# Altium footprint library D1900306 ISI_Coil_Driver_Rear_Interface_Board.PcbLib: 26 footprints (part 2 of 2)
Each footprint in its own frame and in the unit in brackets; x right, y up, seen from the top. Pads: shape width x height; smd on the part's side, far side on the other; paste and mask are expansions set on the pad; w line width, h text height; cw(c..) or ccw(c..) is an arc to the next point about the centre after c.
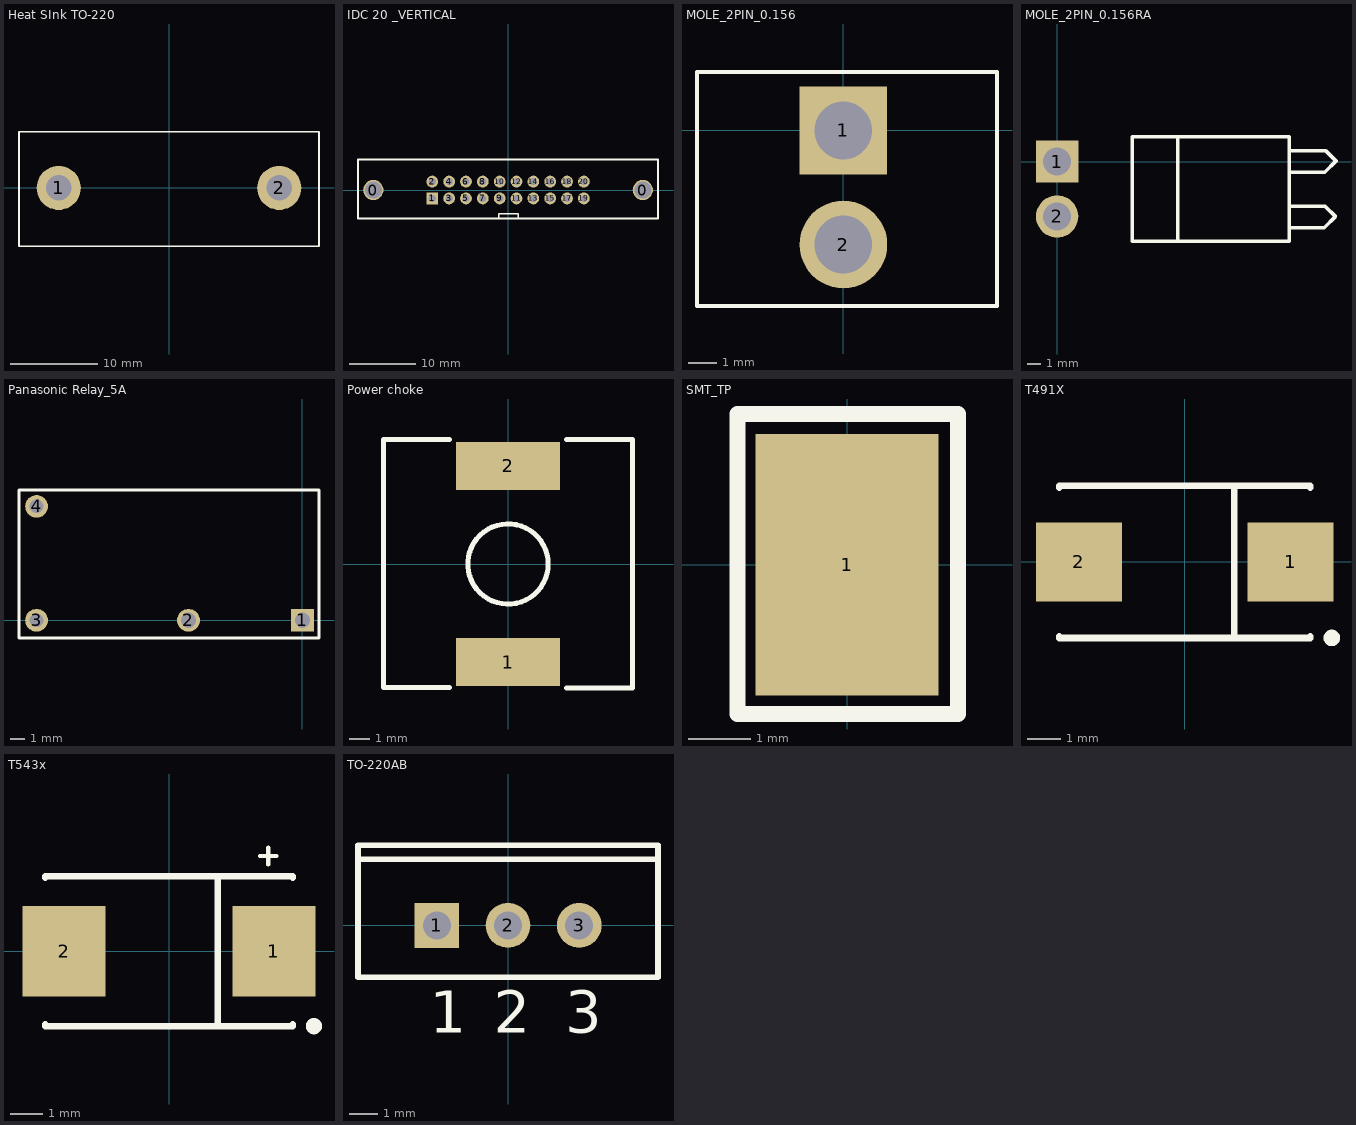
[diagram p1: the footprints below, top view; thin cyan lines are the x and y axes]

## Heat SInk TO-220 [mil]
pads (2):
  round 200 hole 115: 1(-500,0) 2(500,0)
Top Overlay:
  lines w8: -680,-265 680,-265 680,255 -680,255 -680,-265
3D body "T220-38E.step": height 1500, standoff -137.8, extent -669.61,-251.75 669.63,251.65

## IDC 20 _VERTICAL [mil]
pads (22):
  round 120 hole 100: 0(-800,0) 0(800,0)
  rect 70x70 hole 43: 1(-450,-50)
  round 70 hole 43: 2(-450,50) 3(-350,-50) 4(-350,50) 5(-250,-50) 6(-250,50) 7(-150,-50) 8(-150,50) 9(-50,-50) 10(-50,50) 11(50,-50) 12(50,50) 13(150,-50) 14(150,50) 15(250,-50) 16(250,50) 17(350,-50) 18(350,50) 19(450,-50) 20(450,50)
Top Overlay:
  lines w10: -55,-170 -55,-140 40,-140 60,-140 60,-170
  lines w12: -891,-170 890,-170 890,182 -891,182 -891,-170
3D body "Amph 20POS 2.54mm (71918-120LF).stp": height 1043.74, standoff -136.9, extent -880.92,-159 878.92,171.71

## MOLE_2PIN_0.156 [mil]
pads (2):
  rect 120x120 hole 79: 1(0,0)
  round 120 hole 79: 2(0,-156)
Top Overlay:
  lines w5: -200,-240 210,-240 210,80 -200,80 -200,-240
3D body "MOLEX 2pin 3.96mm (026614020).stp": height 580.5, standoff -139.5, extent -193.48,-230.75 200.52,75.25

## MOLE_2PIN_0.156RA [mil]
pads (2):
  rect 120x120 hole 79: 1(0,0)
  round 120 hole 79: 2(0,-156)
Top Overlay:
  lines w10: 343,-226 343,70 ; 659,-187.5 758.5,-187.5 790,-156 761.5,-127.5 659,-127.5 ; 659,-30 760,-30 791.5,1.5 763,30 659,30 ; 213,-226 659,-226 659,70 213,70 213,-226
3D body "MOLEX 2pin 90deg 3.96mm (026615020).stp": height 394.5, standoff -155.5, extent -12.75,-230 802.75,76

## Panasonic Relay_5A [mil]
pads (4):
  rect 60x60 hole 40: 1(0,0)
  round 60 hole 40: 2(-300,0)
  round 60 hole 36: 3(-700,0) 4(-700,300)
Top Overlay:
  lines w7.87: -746.3,343.2 43.7,343.2 43.7,-46.8
  lines w8: -746.3,343.2 -746.3,-46.8 43.7,-46.8
3D body "RELAY_JQ1A.step": height 630.12, standoff -100, extent -744.02,-47 42.98,347.01

## Power choke [mm] "PCD1572-ND"
pads (2):
  rect 5.2x2.4 smd: 1(0,-4.9) 2(0,4.9)
Top Overlay:
  circle w0.254: c0,0 r2.009
  lines w0.254: -2.921,-6.172 -6.223,-6.172 -6.223,6.223 -2.921,6.223 ; 2.921,-6.198 6.223,-6.198 6.223,6.223 2.921,6.223
3D body "WE-PD.stp": height 9.46, standoff 0.01, extent -6,-6 6,6

## SMT_TP [mil] "Surface Mount Test Point"
pads (1):
  rect 115x165 smd: 1(0,0)
Top Overlay:
  lines w10: -69,-94 -69,95 70,95 70,-94 -69,-94
3D body "Test Point (5019).STEP": height 90.5, standoff 0.5, extent -39.96,-75 39.96,75

## T491X [mm]
pads (2):
  rect 2.6x2.4 smd: 1(3.2,0) 2(-3.2,0)
Top Overlay:
  circle w0.25: c4.45,-2.3 r0.125
  lines w0.2: -3.8,-2.25 -3.8,-2.3 3.8,-2.3 3.8,-2.25 ; -3.8,2.25 -3.8,2.3 3.8,2.3 3.8,2.25 ; 1.5,-2.3 1.5,2.3
3D body "Tantilum Case X.stp": height 4.31, standoff 0.01, extent -3.8,-2.314 3.8,2.286

## T543x [mm]
pads (2):
  rect 2.55x2.77 smd: 1(3.22,0) 2(-3.22,0)
Top Overlay:
  circle w0.25: c4.45,-2.3 r0.125
  lines w0.127: 2.794,2.921 3.302,2.921 ; 3.048,2.667 3.048,3.175
  lines w0.2: -3.8,-2.25 -3.8,-2.3 3.8,-2.3 3.8,-2.25 ; -3.8,2.25 -3.8,2.3 3.8,2.3 3.8,2.25 ; 1.5,-2.3 1.5,2.3
3D body "Tantilum Case X.stp": height 4.31, standoff 0.01, extent -3.8,-2.314 3.8,2.286

## TO-220AB [mm] "TO, Thru-Hole, Vertical, Heatsink Mounted; 3 In-Line Leads; Pitch 2.54 mm"
height 19.3
pads (3):
  rect 1.6x1.6 hole 1: 1(-2.54,0)
  round 1.6 hole 1: 2(0,0) 3(2.54,0)
Top Overlay:
  lines w0.2: -5.35,2.35 5.35,2.35 ; -5.35,-1.85 -5.35,2.85 5.35,2.85 5.35,-1.85 -5.35,-1.85
  text "3" at 2.04,-3.825 h1.5
  text "1" at -2.79,-3.825 h1.5
  text "2" at -0.5,-3.825 h1.5
3D body "TO-220-3.step": height 22.56, standoff -4.01, extent -5.271,-1.842 5.271,2.858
